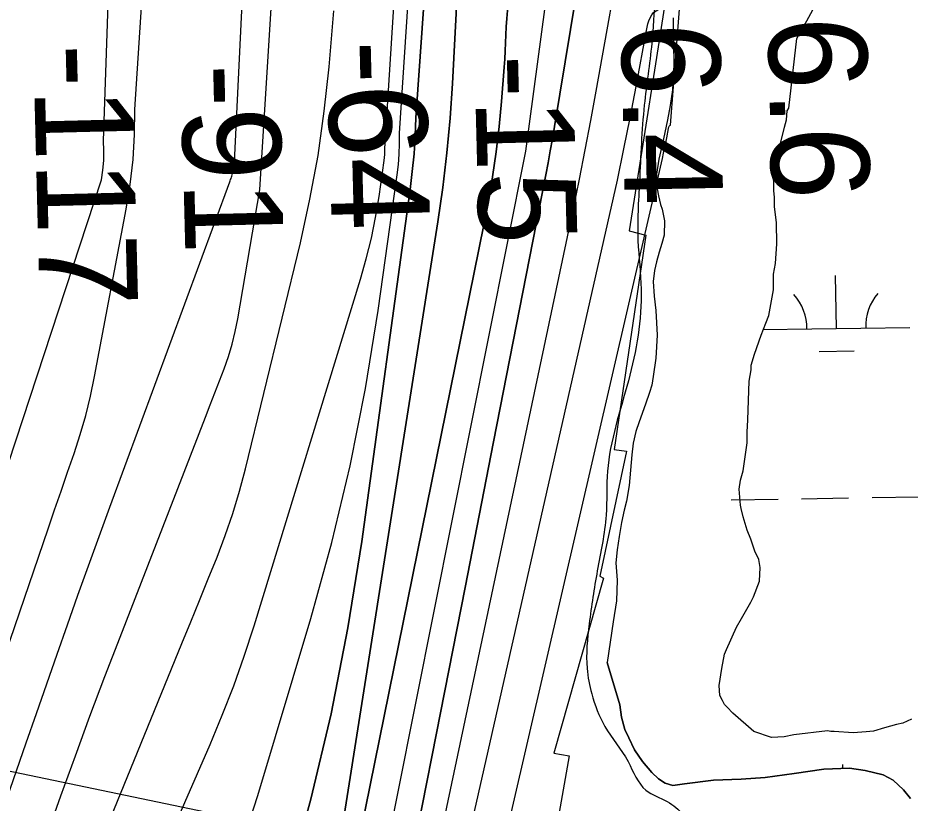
# Model space of a CAD drawing. Extents: x 3807117 to 3845308, y 337856 to 363736.
# Drawn here: x 3833411 to 3834019, y 345040 to 345575 of the extents above; entities that cross this region are included whole.
import ezdxf

# ---------------------------------------------------------------- set-up
doc = ezdxf.new("R2010")
doc.units = 0
for name, color, linetype in [('V-RIVR-EDGE', 7, 'Continuous'), ('V-RIVR-RANG', 7, 'Continuous'), ('V-RRAP-RVMT', 7, 'Continuous'), ('V-SITE-VEGE', 7, 'Continuous'), ('V-TOPO-DPTH', 7, 'Continuous'), ('V-TOPO-MAJR', 7, 'Continuous'), ('V-TOPO-MINR', 7, 'Continuous'), ('V-TOPO-SHOR', 7, 'Continuous'), ('V-TOPO-WATR', 7, 'Continuous'), ('V-WETL-SWMP', 7, 'Continuous')]:
    doc.layers.add(name, color=color, linetype=linetype)

msp = doc.modelspace()

# ---------------------------------------------------------------- linework, layer by layer
at = {"layer": 'V-RIVR-EDGE'}
msp.add_spline([(3833993.63, 346073.15), (3834014.82, 346049.13), (3834027.93, 346045.03), (3834044.2, 346044.54), (3834056.42, 346046.77), (3834063.2, 346046.75), (3834065.46, 346045.39), (3834066.76, 346025.04), (3834070.78, 346004.68), (3834083.34, 345964.41), (3834083.78, 345960.79), (3834080.16, 345959.89), (3834071.58, 345963.98), (3834066.61, 345963.09), (3834057.1, 345958.14), (3834056.17, 345945.94), (3834053.89, 345939.61), (3834045.29, 345936.01), (3834032.17, 345933.79), (3834020.87, 345934.27), (3834010.46, 345930.67), (3833991.44, 345919.42), (3833968.34, 345903.65), (3833937.09, 345880.21), (3833918.03, 345855.85), (3833899.87, 345825.6), (3833887.57, 345788.55), (3833879.36, 345756.47), (3833874.27, 345710.36), (3833869.21, 345675.1), (3833852.34, 345618.62), (3833845.48, 345588.35), (3833842.69, 345557.15), (3833837.61, 345515.12), (3833834.32, 345463.13), (3833833.31, 345422.89), (3833835.49, 345389.87), (3833826.75, 345327.5), (3833812.58, 345266.04), (3833811.6, 345236.2), (3833805.63, 345198.23), (3833800.11, 345162.07), (3833798.68, 345131.78), (3833801.81, 345114.59), (3833810.79, 345092.41), (3833826.56, 345068.41), (3833838.72, 345048.94), (3833853.17, 345041.22), (3833864.45, 345032.14), (3833872.11, 345019.46), (3833872.08, 345008.16), (3833866.05, 344947.59), (3833859.08, 344872.55), (3833858.17, 344868.03), (3833853.65, 344868.04), (3833833.32, 344878.03), (3833815.73, 344894.81), (3833804.91, 344906.14), (3833797.68, 344908.87), (3833783.21, 344908.45), (3833736.6, 344893.2), (3833706.24, 344865.69), (3833687.65, 344845.39), (3833676.3, 344827.33), (3833665.38, 344800.68), (3833650.83, 344767.71), (3833632.62, 344715.75), (3833615.31, 344663.8), (3833598.93, 344623.14), (3833579.38, 344582.5), (3833566.62, 344539.57), (3833556.59, 344505.69), (3833525.62, 344416.69), (3833510.59, 344373.77), (3833496.02, 344333.11), (3833486.92, 344308.72), (3833473.26, 344271.22), (3833455.06, 344226.05), (3833441.84, 344180.87), (3833432.72, 344150.15), (3833396.31, 344055.73), (3833377.19, 344001.07), (3833358.09, 343958.61), (3833345.37, 343934.23), (3833328.05, 343879.56), (3833312.99, 343821.72), (3833296.6, 343775.64), (3833286.11, 343739.5), (3833276.03, 343687.07), (3833267.36, 343654.99), (3833255.05, 343614.32), (3833253.24, 343609.33)], degree=3, dxfattribs=at)
at = {"layer": 'V-RIVR-RANG'}
msp.add_line((3834413.93, 344852.16), (3832955.14, 345155.51), dxfattribs=at)
at = {"layer": 'V-RRAP-RVMT'}
for p, q in [((3833858.28, 345627.79), (3833845.9, 345547.63)), ((3833845.9, 345547.63), (3833827.42, 345429.58)), ((3833838.64, 345426.61), (3833817.16, 345280.73)), ((3833827.42, 345429.58), (3833838.64, 345426.61)), ((3833825.56, 345279.57), (3833807.3, 345194.6)), ((3833817.16, 345280.73), (3833825.56, 345279.57)), ((3833807.3, 345194.6), (3833809.78, 345193.13)), ((3833809.78, 345193.13), (3833775.98, 345074.13)), ((3833775.98, 345074.13), (3833786.55, 345072.26)), ((3833786.55, 345072.26), (3833762.19, 344934.4))]:
    msp.add_line(p, q, dxfattribs=at)
at = {"layer": 'V-SITE-VEGE'}
for points in [[(3833907.64, 345285.25), (3833907.63, 345292.63), (3833908.08, 345300.92), (3833908.96, 345327.2), (3833910.33, 345335.04), (3833910.33, 345338.26), (3833912.62, 345345.64), (3833917.21, 345358.55), (3833920.43, 345366.85), (3833922.26, 345371.93), (3833925.46, 345389.45), (3833925.44, 345400.05), (3833926.81, 345407.42), (3833927.72, 345420.79), (3833927.7, 345435.08), (3833926.29, 345446.14), (3833926.29, 345452.59), (3833925.82, 345456.74), (3833925.81, 345463.65), (3833924.42, 345468.26), (3833926.25, 345473.33), (3833927.17, 345477.02), (3833928.55, 345480.25), (3833929, 345483.48), (3833933.12, 345500.08), (3833934.5, 345505.15), (3833934.95, 345511.14), (3833935.87, 345512.98), (3833941.33, 345560.47), (3833948.23, 345572.46), (3833955.12, 345584.91)], [(3834019.47, 345097.38), (3834013.48, 345094.6), (3834009.34, 345093.67), (3834001.04, 345091.35), (3833993.67, 345089.04), (3833988.6, 345088.57), (3833979.85, 345088.1), (3833966.94, 345089), (3833964.64, 345088.99), (3833962.33, 345089.45), (3833939.29, 345086.65), (3833932.84, 345085.26), (3833924.08, 345084.78), (3833912.09, 345088.91), (3833897.79, 345101.34), (3833894.09, 345105.48), (3833892.25, 345107.32), (3833890.86, 345110.08), (3833889.01, 345113.31), (3833888.54, 345120.22), (3833890.37, 345131.74), (3833892.19, 345141.43), (3833893.57, 345144.66), (3833900.46, 345159.88), (3833903.68, 345165.87), (3833910.11, 345176.94), (3833911.95, 345180.63), (3833916.08, 345191.24), (3833916.53, 345200.46), (3833915.6, 345205.99), (3833912.83, 345211.52), (3833910.05, 345219.81), (3833907.73, 345225.8), (3833904.96, 345235.01), (3833903.56, 345240.54), (3833903.1, 345242.84), (3833902.16, 345253.9), (3833903.08, 345259.9), (3833904.91, 345266.35), (3833907.64, 345285.25)]]:
    msp.add_lwpolyline(points, dxfattribs=at)
at = {"layer": 'V-TOPO-DPTH'}
for points in [[(3833755.66, 347826.28), (3833871.59, 347424.5), (3833872.33, 347421.71), (3833872.97, 347418.91), (3833873.49, 347416.08), (3833873.92, 347413.23), (3833781.27, 345841.92), (3833779.51, 345831.67), (3833745.24, 345584.94), (3833744.57, 345579.47), (3833744.03, 345574), (3833743.67, 345568.5), (3833743.44, 345563), (3833743.25, 345557.5), (3833743.01, 345552), (3833742.67, 345546.5), (3833742.28, 345541), (3833740.41, 345517.63), (3833738.79, 345500.49), (3833736.82, 345483.38), (3833734.35, 345466.35), (3833731.53, 345449.36), (3833641.2, 345004.31), (3833528.64, 344650.91)], [(3833528.64, 344650.91), (3833641.2, 345004.31), (3833731.53, 345449.36), (3833734.35, 345466.35), (3833736.82, 345483.38), (3833738.79, 345500.49), (3833740.41, 345517.63), (3833742.28, 345541), (3833742.67, 345546.5), (3833743.01, 345552), (3833743.25, 345557.5), (3833743.44, 345563), (3833743.67, 345568.5), (3833744.03, 345574), (3833744.57, 345579.47), (3833745.24, 345584.94), (3833779.51, 345831.67), (3833781.27, 345841.92), (3833873.92, 347413.23), (3833873.49, 347416.08), (3833872.97, 347418.91), (3833872.33, 347421.71), (3833871.59, 347424.5), (3833755.66, 347826.28)], [(3833740.07, 347669.94), (3833763.23, 347578.84), (3833799.23, 347431.82), (3833803.32, 347413.96), (3833807.03, 347396.02), (3833810.2, 347377.98), (3833812.99, 347359.86), (3833682.02, 345506.5), (3833681.6, 345494.27), (3833680.88, 345482.07), (3833679.72, 345469.9), (3833678.28, 345457.75), (3833645.33, 345218.27), (3833635.85, 345159.35), (3833624.6, 345100.82), (3833610.7, 345042.86), (3833595.02, 344985.28), (3833517.81, 344796.65), (3833506.15, 344775.51), (3833494.99, 344754.1)], [(3833494.99, 344754.1), (3833506.15, 344775.51), (3833517.81, 344796.65), (3833595.02, 344985.28), (3833610.7, 345042.86), (3833624.6, 345100.82), (3833635.85, 345159.35), (3833645.33, 345218.27), (3833678.28, 345457.75), (3833679.72, 345469.9), (3833680.88, 345482.07), (3833681.6, 345494.27), (3833682.02, 345506.5), (3833812.99, 347359.86), (3833810.2, 347377.98), (3833807.03, 347396.02), (3833803.32, 347413.96), (3833799.23, 347431.82), (3833763.23, 347578.84), (3833740.07, 347669.94)], [(3833474.86, 344395.5), (3833657.06, 344889.85), (3833676.7, 344988.85), (3833696.26, 345087.87), (3833715.71, 345186.91), (3833735.08, 345285.96), (3833770.54, 345467.77), (3833772.09, 345475.93), (3833773.6, 345484.11), (3833775.04, 345492.29), (3833776.42, 345500.49), (3833809.14, 345698.76), (3833810.34, 345704.89), (3833811.79, 345710.94), (3833894.42, 347400.53), (3833892.67, 347412.89), (3833890.64, 347425.21), (3833888.2, 347437.45), (3833885.48, 347449.64), (3833840.37, 347637.08)], [(3833840.37, 347637.08), (3833885.48, 347449.64), (3833888.2, 347437.45), (3833890.64, 347425.21), (3833892.67, 347412.89), (3833894.42, 347400.53), (3833811.79, 345710.94), (3833810.34, 345704.89), (3833809.14, 345698.76), (3833776.42, 345500.49), (3833775.04, 345492.29), (3833773.6, 345484.11), (3833772.09, 345475.93), (3833770.54, 345467.77), (3833735.08, 345285.96), (3833715.71, 345186.91), (3833696.26, 345087.87), (3833676.7, 344988.85), (3833657.06, 344889.85), (3833474.86, 344395.5)], [(3833471.33, 344282.24), (3833688.78, 344887.19), (3833819.31, 345464.11), (3833823.75, 345485.3), (3833827.95, 345506.54), (3833832, 345527.81), (3833839.04, 345565.96), (3833839.52, 345568.16), (3833840.09, 345570.34), (3833840.78, 345572.48), (3833841.57, 345574.59), (3833842.63, 345576.47), (3833843.94, 345578.1), (3833845.6, 345579.36), (3833847.51, 345580.38), (3833948.78, 347392.97)], [(3833847.92, 347337.23), (3833721.96, 345785.95), (3833719.83, 345769.81), (3833718.09, 345753.62), (3833716.94, 345737.39), (3833716.19, 345721.12), (3833715.67, 345704.83), (3833715.07, 345688.54), (3833714.36, 345672.25), (3833713.57, 345655.97), (3833707, 345529.88), (3833705.4, 345506.24), (3833703.3, 345482.66), (3833700.47, 345459.15), (3833697.14, 345435.69), (3833630.63, 345014.55), (3833496.97, 344647.56)], [(3833496.97, 344647.56), (3833630.63, 345014.55), (3833697.14, 345435.69), (3833700.47, 345459.15), (3833703.3, 345482.66), (3833705.4, 345506.24), (3833707, 345529.88), (3833713.57, 345655.97), (3833714.36, 345672.25), (3833715.07, 345688.54), (3833715.67, 345704.83), (3833716.19, 345721.12), (3833716.94, 345737.39), (3833718.09, 345753.62), (3833719.83, 345769.81), (3833721.96, 345785.95), (3833847.92, 347337.23)]]:
    msp.add_lwpolyline(points, dxfattribs=at)
at = {"layer": 'V-TOPO-MAJR'}
for points in [[(3833451.6, 344762.09), (3833463.34, 344791.4), (3833475.74, 344820.44), (3833488.59, 344849.29), (3833493.89, 344860.83), (3833504.54, 344883.71), (3833515.35, 344906.52), (3833526.39, 344929.22), (3833537.58, 344951.85), (3833548.27, 344974.66), (3833558.15, 344997.8), (3833566.81, 345021.42), (3833574.66, 345045.36), (3833610.67, 345165.79), (3833624.88, 345217.56), (3833637.51, 345269.68), (3833647.77, 345322.32), (3833656.45, 345375.3), (3833669.42, 345467.64), (3833670.24, 345474.72), (3833670.82, 345481.82), (3833671.06, 345488.93), (3833671.06, 345496.06), (3833794.41, 347371.37)], [(3833376.87, 345066.01), (3833431.81, 345226.82), (3833436.21, 345239.66), (3833440.63, 345252.49), (3833445.07, 345265.31), (3833449.52, 345278.13), (3833453.69, 345291.02), (3833457.47, 345304.02), (3833460.68, 345317.17), (3833463.49, 345330.42), (3833485, 345444.3), (3833487.66, 345461.15), (3833489.64, 345478.05), (3833490.6, 345495.03), (3833490.88, 345512.08), (3833600.01, 347191.1)]]:
    msp.add_lwpolyline(points, dxfattribs=at)
at = {"layer": 'V-TOPO-MINR'}
for points in [[(3833528.64, 344650.91), (3833641.2, 345004.31), (3833731.53, 345449.36), (3833734.35, 345466.35), (3833736.82, 345483.38), (3833738.79, 345500.49), (3833740.41, 345517.63), (3833742.28, 345541), (3833742.67, 345546.5), (3833743.01, 345552), (3833743.25, 345557.5), (3833743.44, 345563), (3833743.67, 345568.5), (3833744.03, 345574), (3833744.57, 345579.47), (3833745.24, 345584.94), (3833779.51, 345831.67), (3833781.27, 345841.92), (3833873.92, 347413.23), (3833873.49, 347416.08), (3833872.97, 347418.91), (3833872.33, 347421.71), (3833871.59, 347424.5), (3833755.66, 347826.28)], [(3833483.23, 344461), (3833657.1, 344983), (3833757.1, 345483.71), (3833794.62, 345764.9), (3833796, 345773.12), (3833797.73, 345781.25), (3833800.01, 345789.24), (3833884.18, 347406.88), (3833883.06, 347414.48), (3833881.73, 347422.04), (3833880.09, 347429.53), (3833878.23, 347436.99), (3833805.11, 347706.43)], [(3833473.9, 344340.17), (3833668.71, 344873.67), (3833686.7, 344959.27), (3833789.35, 345444.83), (3833793.46, 345464.75), (3833797.44, 345484.69), (3833801.23, 345504.67), (3833804.88, 345524.68), (3833824.04, 345632.44), (3833824.9, 345636.56), (3833825.93, 345640.64), (3833827.19, 345644.65), (3833920.97, 347383.61), (3833917.74, 347408.63), (3833913.95, 347433.54), (3833909.29, 347458.32), (3833904.06, 347482.99), (3833884.9, 347566.26), (3833868.88, 347632.29), (3833851.82, 347698.03)], [(3833494.99, 344754.1), (3833506.15, 344775.51), (3833517.81, 344796.65), (3833595.02, 344985.28), (3833610.7, 345042.86), (3833624.6, 345100.82), (3833635.85, 345159.35), (3833645.33, 345218.27), (3833678.28, 345457.75), (3833679.72, 345469.9), (3833680.88, 345482.07), (3833681.6, 345494.27), (3833682.02, 345506.5), (3833812.99, 347359.86), (3833810.2, 347377.98), (3833807.03, 347396.02), (3833803.32, 347413.96), (3833799.23, 347431.82), (3833763.23, 347578.84), (3833740.07, 347669.94)], [(3833468.24, 345464.24), (3833469.17, 345470.88), (3833469.74, 345477.53), (3833469.79, 345484.21), (3833469.48, 345490.9), (3833529.67, 347251.32), (3833532.87, 347276.32), (3833534.71, 347301.37), (3833534.52, 347326.48), (3833532.97, 347351.64), (3833529.79, 347382.53), (3833524.69, 347422.77), (3833518.34, 347462.78), (3833510.09, 347502.45), (3833500.59, 347541.88), (3833489.98, 347581.1), (3833479.16, 347620.25), (3833468.01, 347659.31)], [(3833401.98, 344936.67), (3833411.64, 344963.8), (3833421.29, 344990.92), (3833430.96, 345018.05), (3833440.62, 345045.18), (3833450.4, 345072.26), (3833460.34, 345099.29), (3833470.5, 345126.23), (3833480.81, 345153.11), (3833538.98, 345302.86), (3833542.17, 345311.08), (3833545.34, 345319.31), (3833548.51, 345327.54), (3833551.66, 345335.78), (3833554.56, 345344.09), (3833557.12, 345352.49), (3833559.19, 345361.02), (3833560.93, 345369.65), (3833575.95, 345457.41), (3833694.63, 347356.6), (3833692.89, 347365.13), (3833690.81, 347373.61), (3833615.3, 347645.21)], [(3833474.86, 344395.5), (3833657.06, 344889.85), (3833676.7, 344988.85), (3833696.26, 345087.87), (3833715.71, 345186.91), (3833735.08, 345285.96), (3833770.54, 345467.77), (3833772.09, 345475.93), (3833773.6, 345484.11), (3833775.04, 345492.29), (3833776.42, 345500.49), (3833809.14, 345698.76), (3833810.34, 345704.89), (3833811.79, 345710.94), (3833894.42, 347400.53), (3833892.67, 347412.89), (3833890.64, 347425.21), (3833888.2, 347437.45), (3833885.48, 347449.64), (3833840.37, 347637.08)], [(3833575.64, 344292.26), (3833849.9, 345478.81), (3833850.69, 345482.33), (3833851.46, 345485.86), (3833852.18, 345489.4), (3833852.87, 345492.94), (3833854.07, 345499.31), (3833854.15, 345499.67), (3833854.25, 345500.03), (3833854.37, 345500.38), (3833854.5, 345500.72), (3833854.68, 345501.02), (3833854.9, 345501.27), (3833855.18, 345501.45), (3833855.51, 345501.58), (3834004.46, 347422.46), (3834002.61, 347443.21), (3834000.33, 347463.91), (3833997.4, 347484.52), (3833994.03, 347505.08), (3833970.36, 347636.66)], [(3833516.28, 345020.93), (3833524.88, 345040.67), (3833533.49, 345060.4), (3833542.13, 345080.12), (3833550.42, 345099.96), (3833558.25, 345119.98), (3833565.39, 345140.26), (3833572.05, 345160.71), (3833644.44, 345396.64), (3833648.35, 345410.54), (3833651.84, 345424.54), (3833654.67, 345438.68), (3833657.07, 345452.92), (3833660.63, 345477.51), (3833660.86, 345479.53), (3833661.01, 345481.56), (3833661.05, 345483.59), (3833661.01, 345485.63), (3833781.33, 347382.78)], [(3833496.97, 344647.56), (3833630.63, 345014.55), (3833697.14, 345435.69), (3833700.47, 345459.15), (3833703.3, 345482.66), (3833705.4, 345506.24), (3833707, 345529.88), (3833713.57, 345655.97), (3833714.36, 345672.25), (3833715.07, 345688.54), (3833715.67, 345704.83), (3833716.19, 345721.12), (3833716.94, 345737.39), (3833718.09, 345753.62), (3833719.83, 345769.81), (3833721.96, 345785.95), (3833847.92, 347337.23)], [(3833382.12, 344981.39), (3833416.89, 345081.13), (3833423.91, 345101.24), (3833430.94, 345121.34), (3833437.99, 345141.43), (3833445.06, 345161.52), (3833452.17, 345181.59), (3833459.35, 345201.64), (3833466.61, 345221.66), (3833473.93, 345241.66), (3833555.47, 345462.85), (3833555.77, 345463.65), (3833556.06, 345464.45), (3833556.35, 345465.26), (3833556.64, 345466.06), (3833556.91, 345466.87), (3833557.14, 345467.68), (3833557.33, 345468.51), (3833557.48, 345469.35), (3833558.72, 345477.41), (3833558.83, 345478.33), (3833558.91, 345479.25), (3833558.94, 345480.17), (3833558.93, 345481.09), (3833636.07, 347075.6)], [(3833399.65, 344828.08), (3833411.68, 344861.25), (3833423.68, 344894.43), (3833435.67, 344927.62), (3833436.22, 344929.13), (3833448.68, 344963), (3833461.43, 344996.75), (3833474.62, 345030.34), (3833488.09, 345063.81), (3833522.95, 345148.83), (3833528.94, 345163.48), (3833534.92, 345178.14), (3833540.88, 345192.82), (3833546.82, 345207.49), (3833552.42, 345222.28), (3833557.59, 345237.21), (3833562.09, 345252.35), (3833566.16, 345267.63), (3833603.58, 345421.49), (3833610.06, 345451.14), (3833615.63, 345480.95), (3833619.81, 345510.98), (3833623.06, 345541.17), (3833626.27, 345579.19)], [(3832892.2, 343603.92), (3832893.56, 343607.9), (3832911.37, 343661.09), (3832928.72, 343714.42), (3832945.77, 343767.86), (3832949.37, 343779.34), (3832967.78, 343838.65), (3832985.89, 343898.05), (3833003.57, 343957.59), (3833020.96, 344017.21), (3833031.9, 344055.24), (3833043.26, 344096.41), (3833054, 344137.74), (3833063.82, 344179.3), (3833073.03, 344221.01), (3833086.5, 344285.37), (3833088.45, 344295.03), (3833090.3, 344304.7), (3833092.02, 344314.4), (3833093.64, 344324.11), (3833468.24, 345464.24)]]:
    msp.add_lwpolyline(points, dxfattribs=at)
at = {"layer": 'V-TOPO-SHOR'}
for points in [[(3833919.78, 345057.57), (3833903.61, 345056.56), (3833884.68, 345055.74), (3833864.95, 345053.35), (3833857.06, 345052.15), (3833851.74, 345053.72), (3833847.39, 345056.67), (3833842.65, 345061.01), (3833836.33, 345068.49), (3833830.99, 345076.37), (3833827.03, 345084.65), (3833824.46, 345090.37), (3833822.08, 345098.65), (3833820.88, 345107.13), (3833812.39, 345135.91)], [(3834018.79, 345043.21), (3834014.05, 345049.2), (3834007.06, 345055.77), (3834000.15, 345059.43), (3833988.03, 345062.41), (3833977.18, 345063.97), (3833959.82, 345063.35), (3833939.7, 345060.36), (3833919.78, 345057.57)]]:
    msp.add_lwpolyline(points, dxfattribs=at)
at = {"layer": 'V-TOPO-WATR'}
msp.add_lwpolyline([(3833471.33, 344282.24), (3833688.78, 344887.19), (3833819.31, 345464.11), (3833823.75, 345485.3), (3833827.95, 345506.54), (3833832, 345527.81), (3833839.04, 345565.96), (3833839.52, 345568.16), (3833840.09, 345570.34), (3833840.78, 345572.48), (3833841.57, 345574.59), (3833842.63, 345576.47), (3833843.94, 345578.1), (3833845.6, 345579.36), (3833847.51, 345580.38), (3833948.78, 347392.97)], dxfattribs=at)
at = {"layer": 'V-WETL-SWMP'}
for p, q in [((3833857.18, 345574.52), (3833857.6, 345557.65)), ((3833857.6, 345557.65), (3833857.62, 345542.63)), ((3833857.62, 345542.63), (3833856.86, 345525.63)), ((3833856.86, 345525.63), (3833855.29, 345514.95)), ((3833855.29, 345514.95), (3833853.46, 345505.07)), ((3833853.46, 345505.07), (3833850.58, 345492.15)), ((3833850.58, 345492.15), (3833847.44, 345478.44)), ((3833847.44, 345478.44), (3833845.88, 345468.03)), ((3833845.88, 345468.03), (3833845.88, 345463.28)), ((3833845.88, 345463.28), (3833846.29, 345458.15)), ((3833846.29, 345458.15), (3833847.22, 345453.4)), ((3833847.22, 345453.4), (3833848.67, 345447.61)), ((3833848.67, 345447.61), (3833849.73, 345444.31)), ((3833849.73, 345444.31), (3833851.46, 345436.41)), ((3833851.46, 345436.41), (3833851.08, 345426.53)), ((3833851.08, 345426.53), (3833849.64, 345420.99)), ((3833849.64, 345420.99), (3833847.67, 345415.06)), ((3833847.67, 345415.06), (3833845.84, 345408.47)), ((3833845.84, 345408.47), (3833844.66, 345402.67)), ((3833844.66, 345402.67), (3833843.62, 345395.02)), ((3833843.62, 345395.02), (3833844.29, 345385.14)), ((3833968.32, 345363.12), (3833967.78, 345399.11)), ((3833844.29, 345385.14), (3833845.36, 345375.26)), ((3833845.36, 345375.26), (3833846.44, 345358.53)), ((3833846.44, 345358.53), (3833845.41, 345342.84)), ((3833918.33, 345362.37), (3834018.31, 345363.86)), ((3833956.55, 345347.51), (3833980.55, 345347.87)), ((3833845.41, 345342.84), (3833843.71, 345330.45)), ((3833843.71, 345330.45), (3833842.67, 345324.52)), ((3833842.67, 345324.52), (3833841.23, 345319.64)), ((3833841.23, 345319.64), (3833838.47, 345311.73)), ((3833838.47, 345311.73), (3833834.01, 345299.6)), ((3833834.01, 345299.6), (3833831.91, 345293.14)), ((3833831.91, 345293.14), (3833830.08, 345285.1)), ((3833830.08, 345285.1), (3833829.04, 345277.06)), ((3833829.04, 345277.06), (3833827.36, 345256.24)), ((3833827.36, 345256.24), (3833825.4, 345245.7)), ((3833825.4, 345245.7), (3833823.96, 345239.5)), ((3833896.65, 345246.6), (3833928.65, 345247.08)), ((3833944.64, 345247.32), (3833976.64, 345247.8)), ((3833992.64, 345248.03), (3834024.63, 345248.51)), ((3833823.96, 345239.5), (3833822.12, 345231.06)), ((3833822.12, 345231.06), (3833820.43, 345221.57)), ((3833820.43, 345221.57), (3833819.12, 345212.61)), ((3833819.12, 345212.61), (3833818.34, 345203.78)), ((3833818.34, 345203.78), (3833819.15, 345191.79)), ((3833819.15, 345191.79), (3833818.65, 345177.82)), ((3833818.65, 345177.82), (3833816.43, 345163.59)), ((3833816.43, 345163.59), (3833812.39, 345135.91)), ((3833812.39, 345135.91), (3833820.88, 345107.13)), ((3833820.88, 345107.13), (3833822.08, 345098.65)), ((3833822.08, 345098.65), (3833824.46, 345090.37)), ((3833824.46, 345090.37), (3833827.03, 345084.65)), ((3833827.03, 345084.65), (3833830.99, 345076.37)), ((3833830.99, 345076.37), (3833836.33, 345068.49)), ((3833836.33, 345068.49), (3833842.65, 345061.01)), ((3833972.8, 345063.82), (3833972.76, 345066.47)), ((3833842.65, 345061.01), (3833847.39, 345056.67)), ((3833919.78, 345057.57), (3833939.7, 345060.36)), ((3833939.7, 345060.36), (3833959.82, 345063.35)), ((3833959.82, 345063.35), (3833977.18, 345063.97)), ((3833977.18, 345063.97), (3833988.03, 345062.41)), ((3833988.03, 345062.41), (3834000.15, 345059.43)), ((3833847.39, 345056.67), (3833851.74, 345053.72)), ((3833864.95, 345053.35), (3833884.68, 345055.74)), ((3833884.68, 345055.74), (3833903.61, 345056.56)), ((3833903.61, 345056.56), (3833919.78, 345057.57)), ((3834000.15, 345059.43), (3834007.06, 345055.77)), ((3834007.06, 345055.77), (3834014.05, 345049.2)), ((3833851.74, 345053.72), (3833857.06, 345052.15)), ((3833857.06, 345052.15), (3833864.95, 345053.35)), ((3834014.05, 345049.2), (3834018.79, 345043.21))]:
    msp.add_line(p, q, dxfattribs=at)
for centre, start, end in [((3833913.08, 345362.76), 0.08653, 41.63019), ((3834023.55, 345364.42), 140.08653, 181.63019)]:
    msp.add_arc(centre, 35.25, start, end, dxfattribs=at)

# ---------------------------------------------------------------- texts
at = {"layer": 'V-RIVR-RANG'}
for s, rotation, p in [('6.6', 271.14833, (3833921.81, 345574.85)), ('6.4', 271.14833, (3833821.87, 345570.75)), ('-117', 271.43461, (3833421.68, 345556.28)), ('-64', 271.43461, (3833621.68, 345558.67)), ('-15', 271.43461, (3833721.95, 345549.06)), ('-91', 271.43461, (3833522.05, 345542.7))]:
    msp.add_text(s, height=67, rotation=rotation, dxfattribs=at).set_placement(p)

doc.saveas('drawing.dxf')
